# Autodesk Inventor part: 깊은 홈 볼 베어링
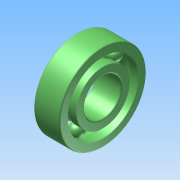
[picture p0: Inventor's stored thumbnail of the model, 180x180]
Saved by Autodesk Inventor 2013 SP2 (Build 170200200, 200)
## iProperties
Created: 2026-07
Part Number: 깊은 홈 볼 베어링
Material: Generic
Document SubType Name: Modeling
Designer: aa
Density: 1 g/cm^3
Author: aa
변환 표준: STEP AP214IS
전처리기: Build: 200, Release: 2013 SP2 Update 6 - Date: Thu 07/17/2014
전송 단위: 밀리미터
불확실성: 0.01
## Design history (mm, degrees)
node "깊은 홈 볼 베어링 62031"
body "Solid1"
node "Solid1_1"
node "Solid1_2"
node "Solid1_3"
node "Solid1_4"
node "Solid1_5"
node "Solid1_6"
node "Solid1_7"
node "Solid1_8"
node "기준1"
node "기준2"
node "기준3"
node "기준4"
node "기준5"
node "기준6"
node "기준7"
node "기준8"
node "기준9"
